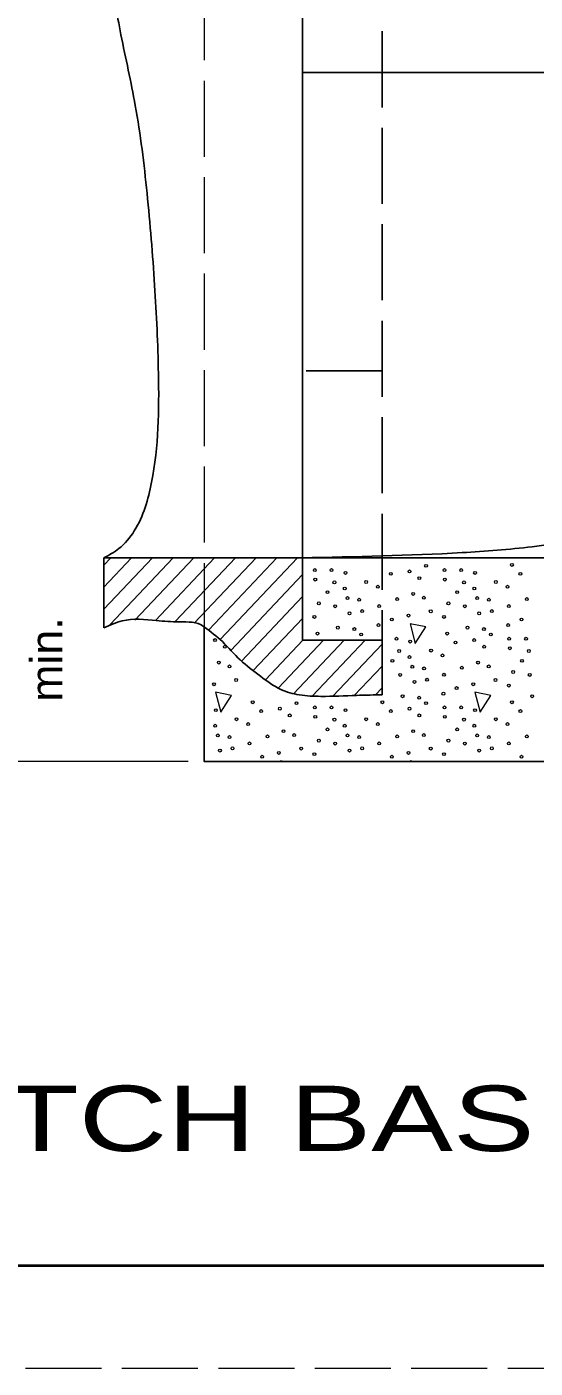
# Model space of a CAD drawing. Extents: x 1083.1 to 1117.1, y 697.4 to 719.4.
# Drawn here: x 1093.04 to 1095.53, y 697.35 to 703.92 of the extents above; entities that cross this region are included whole.
import ezdxf
from ezdxf.enums import TextEntityAlignment as Align

# ---------------------------------------------------------------- set-up
doc = ezdxf.new("R2010")
doc.units = 0
doc.header["$LTSCALE"] = 0.062
doc.linetypes.add('LONG_DASHED', pattern=[7.5, 6, -1.5])
doc.layers.add('1', color=7, linetype='Continuous', lineweight=13)

msp = doc.modelspace()

# ---------------------------------------------------------------- linework, layer by layer
at = {"layer": '1', "linetype": 'LONG_DASHED'}
msp.add_line((1093.91333, 705.54067), (1093.91333, 700.98025), dxfattribs=at)
at = {"layer": '1', "lineweight": 25}
for p, q in [((1094.39417, 701.39083), (1094.39417, 705.15625)), ((1094.39417, 703.69325), (1098.65942, 703.69325)), ((1094.39417, 701.32917), (1094.39417, 701.39083)), ((1093.42242, 701.31858), (1093.42242, 700.97533)), ((1094.39242, 701.31858), (1093.42242, 701.31858)), ((1094.39242, 701.31858), (1099.53092, 701.31858)), ((1094.76475, 700.648), (1094.78358, 700.648))]:
    msp.add_line(p, q, dxfattribs=at)
at = {"layer": '1', "linetype": 'LONG_DASHED', "lineweight": 25}
for p, q in [((1094.78358, 704.36617), (1094.78358, 700.91592)), ((1094.78358, 702.23325), (1094.39417, 702.23325))]:
    msp.add_line(p, q, dxfattribs=at)
at = {"layer": '1'}
for p, q in [((1093.42242, 701.28258), (1093.4565, 701.31867)), ((1093.42242, 701.06758), (1093.6595, 701.31858)), ((1093.42242, 701.17508), (1093.55792, 701.31858)), ((1093.45075, 700.99008), (1093.761, 701.31858)), ((1093.57392, 701.01317), (1093.8625, 701.31858)), ((1093.67442, 701.012), (1093.96392, 701.3185)), ((1093.7705, 701.00625), (1094.0655, 701.31858)), ((1093.86417, 700.998), (1094.167, 701.31858)), ((1093.93608, 700.96667), (1094.2685, 701.31858)), ((1093.99183, 700.91833), (1094.37, 701.31858)), ((1094.04333, 700.86517), (1094.39417, 701.23675)), ((1094.09583, 700.81333), (1094.39417, 701.12925)), ((1094.15292, 700.76642), (1094.39417, 701.02175)), ((1094.21258, 700.72208), (1094.39567, 700.91592)), ((1094.27608, 700.68175), (1094.49725, 700.91592)), ((1094.3505, 700.65317), (1094.59875, 700.91592)), ((1094.4415, 700.64208), (1094.70017, 700.91592)), ((1094.54325, 700.64225), (1094.78358, 700.89667)), ((1094.64725, 700.645), (1094.78358, 700.78917)), ((1094.681, 700.64533), (1094.6785, 700.64583)), ((1094.75125, 700.64758), (1094.78358, 700.68175)), ((1094.78358, 700.648), (1094.78325, 700.648)), ((1093.83458, 700.32125), (1091.946, 700.32125)), ((1094.28592, 700.32467), (1094.28692, 700.32133)), ((1094.3035, 700.32133), (1094.28592, 700.32467)), ((1094.92033, 700.32467), (1094.92125, 700.32133)), ((1094.93792, 700.32133), (1094.92033, 700.32467))]:
    msp.add_line(p, q, dxfattribs=at)
at = {"layer": '1', "linetype": 'LONG_DASHED'}
msp.add_lwpolyline([(1083.12642, 697.35408), (1117.12642, 697.35408), (1117.12642, 719.35408), (1083.12642, 719.35408)], close=True, dxfattribs=at)
at = {"layer": '1', "lineweight": 25}
for points in [[(1116.62642, 697.85408), (1085.12642, 697.85408), (1085.12642, 718.85408)], [(1094.78358, 700.648), (1094.78358, 700.91592), (1094.39417, 700.91592), (1094.39417, 701.32917)], [(1093.91333, 700.98025), (1093.91333, 700.32125), (1099.53092, 700.32125)]]:
    msp.add_lwpolyline(points, dxfattribs=at)
at = {"layer": '1', "lineweight": 40}
msp.add_lwpolyline([(1085.12642, 718.85408), (1116.62642, 718.85408), (1116.62642, 697.85408), (1085.12642, 697.85408)], close=True, dxfattribs=at)
msp.add_lwpolyline([(1085.12642, 718.85408), (1116.62642, 718.85408), (1116.62642, 697.85408), (1085.12642, 697.85408)], close=True, dxfattribs=at)
at = {"layer": '1'}
for points in [[(1094.92033, 700.99625), (1094.94592, 700.899), (1094.99825, 700.98117)], [(1093.96867, 700.6605), (1093.99433, 700.56317), (1094.04658, 700.64533)], [(1095.2375, 700.6605), (1095.26317, 700.56317), (1095.31533, 700.64533)]]:
    msp.add_lwpolyline(points, close=True, dxfattribs=at)
for centre in [(1094.45413, 701.25831), (1094.5364, 701.25831), (1094.60401, 701.24471), (1094.82589, 701.24017), (1094.91751, 701.25198), (1094.99861, 701.27919), (1095.08854, 701.25831), (1095.1708, 701.25831), (1095.23841, 701.24471), (1095.41917, 701.28372), (1095.4603, 701.24017), (1094.45667, 701.21208), (1094.55009, 701.19848), (1094.60058, 701.16853), (1094.70594, 701.20027), (1094.76245, 701.1767), (1094.96578, 701.21902), (1095.09107, 701.21208), (1095.18449, 701.19848), (1095.23498, 701.16853), (1095.34034, 701.20027), (1095.39686, 701.1767), (1094.47354, 701.09571), (1094.51662, 701.1504), (1094.61432, 701.1214), (1094.67168, 701.11318), (1094.85698, 701.11659), (1094.9358, 701.14195), (1094.98804, 701.12292), (1095.10794, 701.09571), (1095.15103, 701.1504), (1095.24872, 701.1214), (1095.30608, 701.11318), (1095.49138, 701.11659), (1094.45213, 701.0295), (1094.55432, 701.0815), (1094.62452, 701.04702), (1094.68622, 701.05793), (1094.76933, 701.08234), (1094.91265, 701.03583), (1095.0214, 701.0567), (1095.08653, 701.0295), (1095.18872, 701.0815), (1095.25893, 701.04702), (1095.32062, 701.05793), (1095.40373, 701.08234), (1094.5669, 700.97694), (1094.64773, 700.96995), (1094.76621, 700.98959), (1094.83123, 701.0168), (1095.2013, 700.97694), (1095.28213, 700.96995), (1095.40061, 700.98959), (1095.46564, 701.0168), (1093.96591, 700.91616), (1094.46756, 700.9479), (1094.68141, 700.94336), (1094.8536, 700.92248), (1094.92121, 700.90888), (1095.10196, 700.9479), (1095.1431, 700.90435), (1095.23471, 700.91616), (1095.31581, 700.94336), (1095.40574, 700.92248), (1095.488, 700.92248), (1094.01418, 700.88319), (1094.86729, 700.86265), (1094.91778, 700.83271), (1095.02314, 700.86444), (1095.07965, 700.84088), (1095.28298, 700.88319), (1095.40828, 700.87625), (1095.50169, 700.86265), (1093.9842, 700.80612), (1094.03643, 700.78709), (1094.83382, 700.81457), (1094.93152, 700.78558), (1094.98888, 700.77735), (1095.17418, 700.78077), (1095.25301, 700.80612), (1095.30524, 700.78709), (1095.46823, 700.81457), (1093.96105, 700.7), (1094.06979, 700.72088), (1094.87152, 700.74567), (1094.94173, 700.71119), (1095.00342, 700.72211), (1095.08653, 700.74651), (1095.22985, 700.7), (1095.3386, 700.72088), (1095.42514, 700.75989), (1095.50592, 700.74567), (1094.8841, 700.64112), (1094.96493, 700.63412), (1095.08341, 700.65377), (1095.14843, 700.68097), (1095.40373, 700.69368), (1095.5185, 700.64112), (1093.96961, 700.57306), (1094.15036, 700.61207), (1094.19149, 700.56853), (1094.28311, 700.58034), (1094.36421, 700.60754), (1094.45413, 700.58666), (1094.5364, 700.58666), (1094.60401, 700.57306), (1094.78476, 700.61207), (1094.82589, 700.56853), (1094.91751, 700.58034), (1094.99861, 700.60754), (1095.08854, 700.58666), (1095.1708, 700.58666), (1095.23841, 700.57306), (1095.41917, 700.61207), (1095.4603, 700.56853), (1094.07154, 700.52862), (1094.12805, 700.50505), (1094.33138, 700.54737), (1094.45667, 700.54043), (1094.55009, 700.52683), (1094.70594, 700.52862), (1094.76245, 700.50505), (1094.96578, 700.54737), (1095.09107, 700.54043), (1095.18449, 700.52683), (1095.34034, 700.52862), (1095.39686, 700.50505), (1093.96617, 700.49688), (1093.97992, 700.44976), (1094.03728, 700.44153), (1094.22258, 700.44494), (1094.3014, 700.4703), (1094.35363, 700.45127), (1094.51662, 700.47875), (1094.60058, 700.49688), (1094.61432, 700.44976), (1094.67168, 700.44153), (1094.85698, 700.44494), (1094.9358, 700.4703), (1094.98804, 700.45127), (1095.15103, 700.47875), (1095.23498, 700.49688), (1095.24872, 700.44976), (1095.30608, 700.44153), (1095.49138, 700.44494), (1093.99012, 700.37537), (1094.05182, 700.38628), (1094.13492, 700.41069), (1094.38699, 700.38505), (1094.47354, 700.42406), (1094.55432, 700.40985), (1094.62452, 700.37537), (1094.68622, 700.38628), (1094.76933, 700.41069), (1095.0214, 700.38505), (1095.10794, 700.42406), (1095.18872, 700.40985), (1095.25893, 700.37537), (1095.32062, 700.38628), (1095.40373, 700.41069), (1094.19683, 700.34515), (1094.27825, 700.36418), (1094.45213, 700.35785), (1094.83123, 700.34515), (1094.91265, 700.36418), (1095.08653, 700.35785), (1095.46564, 700.34515)]:
    msp.add_ellipse(centre, major_axis=(0, 0.00718), ratio=0.944544, dxfattribs=at)
at = {"layer": '1', "lineweight": 25}
for points in [[(1093.42242, 701.31858), (1093.49558, 701.36367), (1093.57083, 701.45033), (1093.65575, 701.68783), (1093.689, 702.22), (1093.6705, 702.652), (1093.63342, 703.10225), (1093.57592, 703.53125), (1093.5055, 703.87767), (1093.4455, 704.18275), (1093.39258, 704.39517)], [(1098.65942, 703.69325), (1098.61475, 703.28575), (1098.42725, 702.85475), (1098.07042, 702.46242), (1097.75942, 702.19125), (1097.49867, 702.02658), (1097.21508, 701.87658), (1097.01842, 701.78933), (1096.61592, 701.62958), (1096.06242, 701.47458), (1095.51817, 701.37292), (1095.17508, 701.34383), (1094.39242, 701.31858)], [(1093.42242, 700.97533), (1093.51217, 701.01025), (1093.6785, 701.01192), (1093.79175, 701.00475), (1093.90975, 700.98317), (1093.91392, 700.97975)], [(1093.91392, 700.97975), (1094.00183, 700.90858), (1094.08933, 700.81875), (1094.18792, 700.73942), (1094.28833, 700.6745), (1094.3785, 700.648), (1094.48433, 700.64075), (1094.65892, 700.64533), (1094.76592, 700.648)]]:
    msp.add_spline(points, degree=3, dxfattribs=at)

# ---------------------------------------------------------------- texts
at = {"layer": '1', "width": 1.05}
msp.add_text('min.', height=0.156, rotation=90, dxfattribs=at).set_placement((1093.21892, 700.82075), align=Align.CENTER)
at = {"layer": '1', "width": 1.4}
msp.add_text('CATCH BASINS No. 2-3 & No. 2-4', height=0.32, dxfattribs=at).set_placement((1096.72875, 698.41617), align=Align.CENTER)

doc.saveas('drawing.dxf')
